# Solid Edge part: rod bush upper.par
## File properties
Author: Robert a Rhodes jr
Template: Normal.par
Last saved by: CADCIM
Revision: 4
Application: Solid Edge
Accuracy: 0.99
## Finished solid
Body 1: solid body, 4 faces, 4 edges, 0 vertices.
  Faces by surface: cylinder 2, plane 2
  Edges by curve: circle 4
Bounding box of the edges (mm): 24.000 x 24.000 x 42.000, from (-12, -12, -42) to (12, 12, 0).
Cylindrical faces by radius (mm): R11 x1, R12 x1
Planar faces by outward normal: +z 1, -z 1
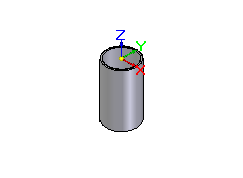
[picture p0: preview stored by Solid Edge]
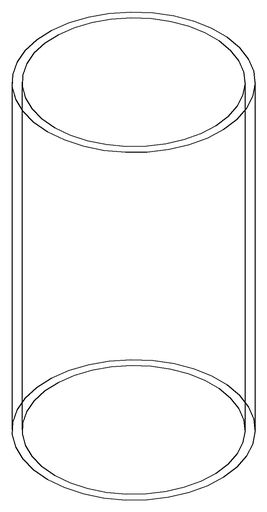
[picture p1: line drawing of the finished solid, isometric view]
